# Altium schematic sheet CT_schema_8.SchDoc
size 278 x 170 mm
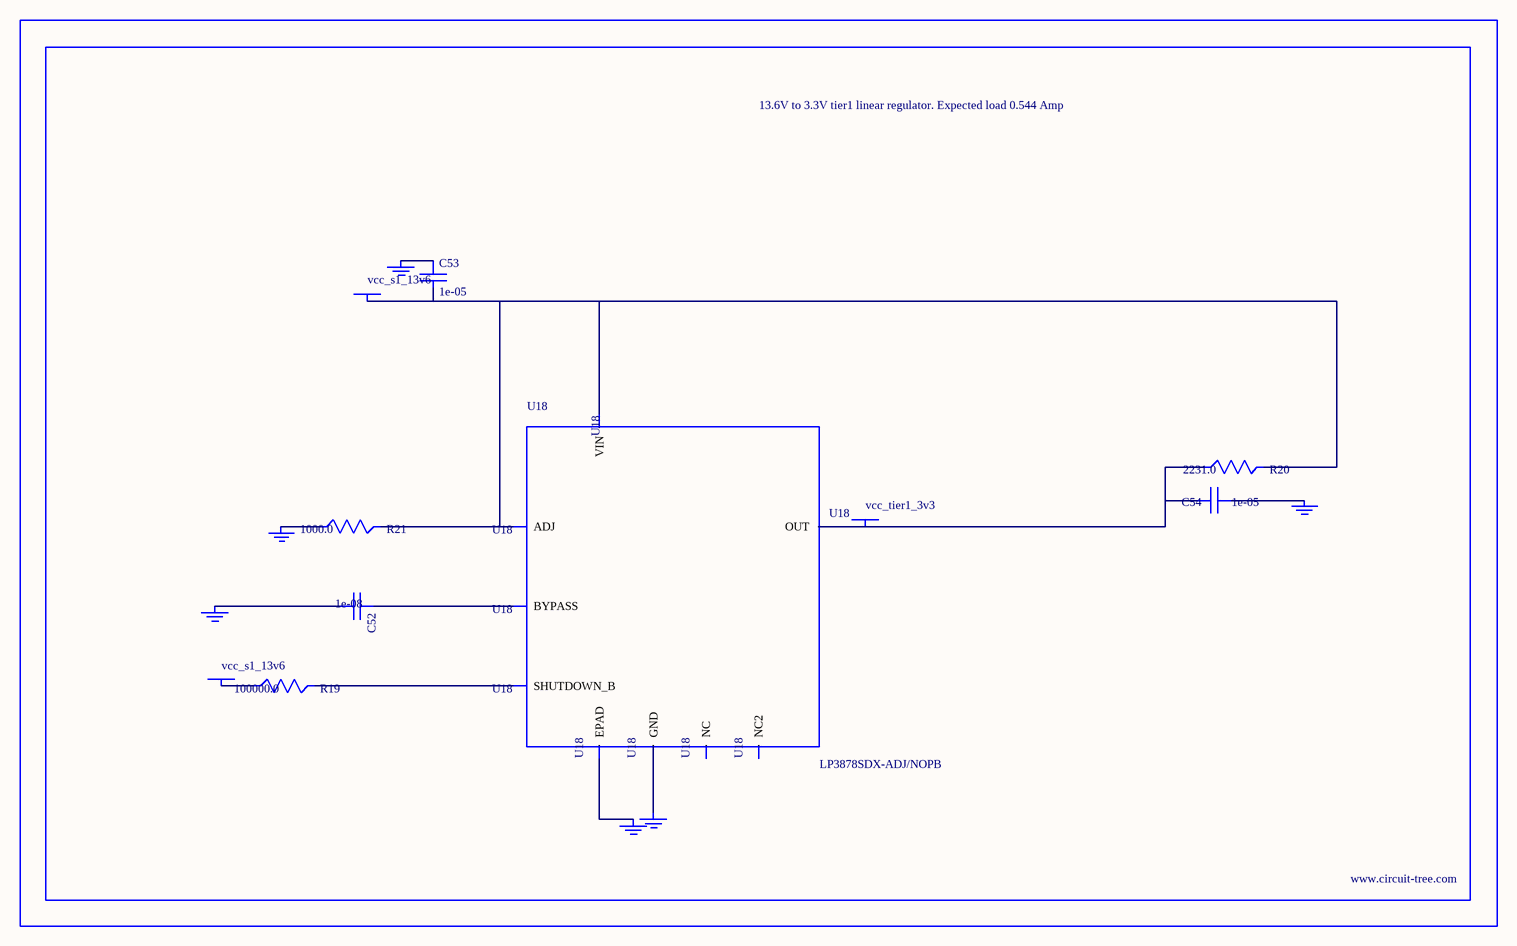
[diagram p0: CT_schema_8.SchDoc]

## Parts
BORDER7  (no value)
C52  1e-08  [C0402]
C53  1e-05  [C1210]
C54  1e-05  [C1210]
GND_INSTANCE_7_0  (no value)
GND_INSTANCE_7_1  (no value)
GND_INSTANCE_7_2  (no value)
GND_INSTANCE_7_3  (no value)
GND_INSTANCE_7_4  (no value)
GND_INSTANCE_7_5  (no value)
POWER_INSTANCE_7_0  vcc_s1_13v6
POWER_INSTANCE_7_1  vcc_s1_13v6
POWER_INSTANCE_7_2  vcc_tier1_3v3
R19  100000.0  [R0603]
R20  2231.0  [R0603]
R21  1000.0  [R0603]
U18  LP3878SDX-ADJ/NOPB  [WSON-8]

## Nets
NetC52_1: C52.1 U18.1(BYPASS)
NetC52_2: C52.2 GND_INSTANCE_7_0.0(GND)
NetC53_1: C53.1 GND_INSTANCE_7_1.0(GND)
NetC53_2: C53.2 POWER_INSTANCE_7_0.0(PWR) R20.2 R21.2 U18.4(VIN) U18.6(ADJ)
NetC54_1: C54.1 GND_INSTANCE_7_2.0(GND)
NetC54_2: C54.2 POWER_INSTANCE_7_2.0(PWR) R20.1 U18.5(OUT)
NetGND_INSTANCE_7_3_0: GND_INSTANCE_7_3.0(GND) R21.1
NetGND_INSTANCE_7_4_0: GND_INSTANCE_7_4.0(GND) U18.PAD(EPAD)
NetGND_INSTANCE_7_5_0: GND_INSTANCE_7_5.0(GND) U18.3(GND)
NetPOWER_INSTANCE_7_1_0: POWER_INSTANCE_7_1.0(PWR) R19.1
NetR19_2: R19.2 U18.8(SHUTDOWN_B)

Not connected (* = marked no-connect by the designer): U18 2(NC) 7(NC2)

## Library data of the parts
BORDER7 = BORDER_PAGE7
C52 = C0402C103K3RAC
C53 = C1210C106K5PACTU
C54 = GRM32DR61E106MA12L
GND_INSTANCE_7_0-GND_INSTANCE_7_5 = GND
POWER_INSTANCE_7_0-POWER_INSTANCE_7_2 = PWR
R19 = RC0603JR-07100KL
R20 = R20
R21 = RC0603JR-071KL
